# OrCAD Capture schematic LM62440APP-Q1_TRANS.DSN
size D; title: LM62440APP-Q1 Automotive 3-V to 36-V, 4-A, Low EMI; rev: 1.0; note: Datasheet:SNVSAW8B       EVM:SNVU622; note: Synchronous Step-Down Converter
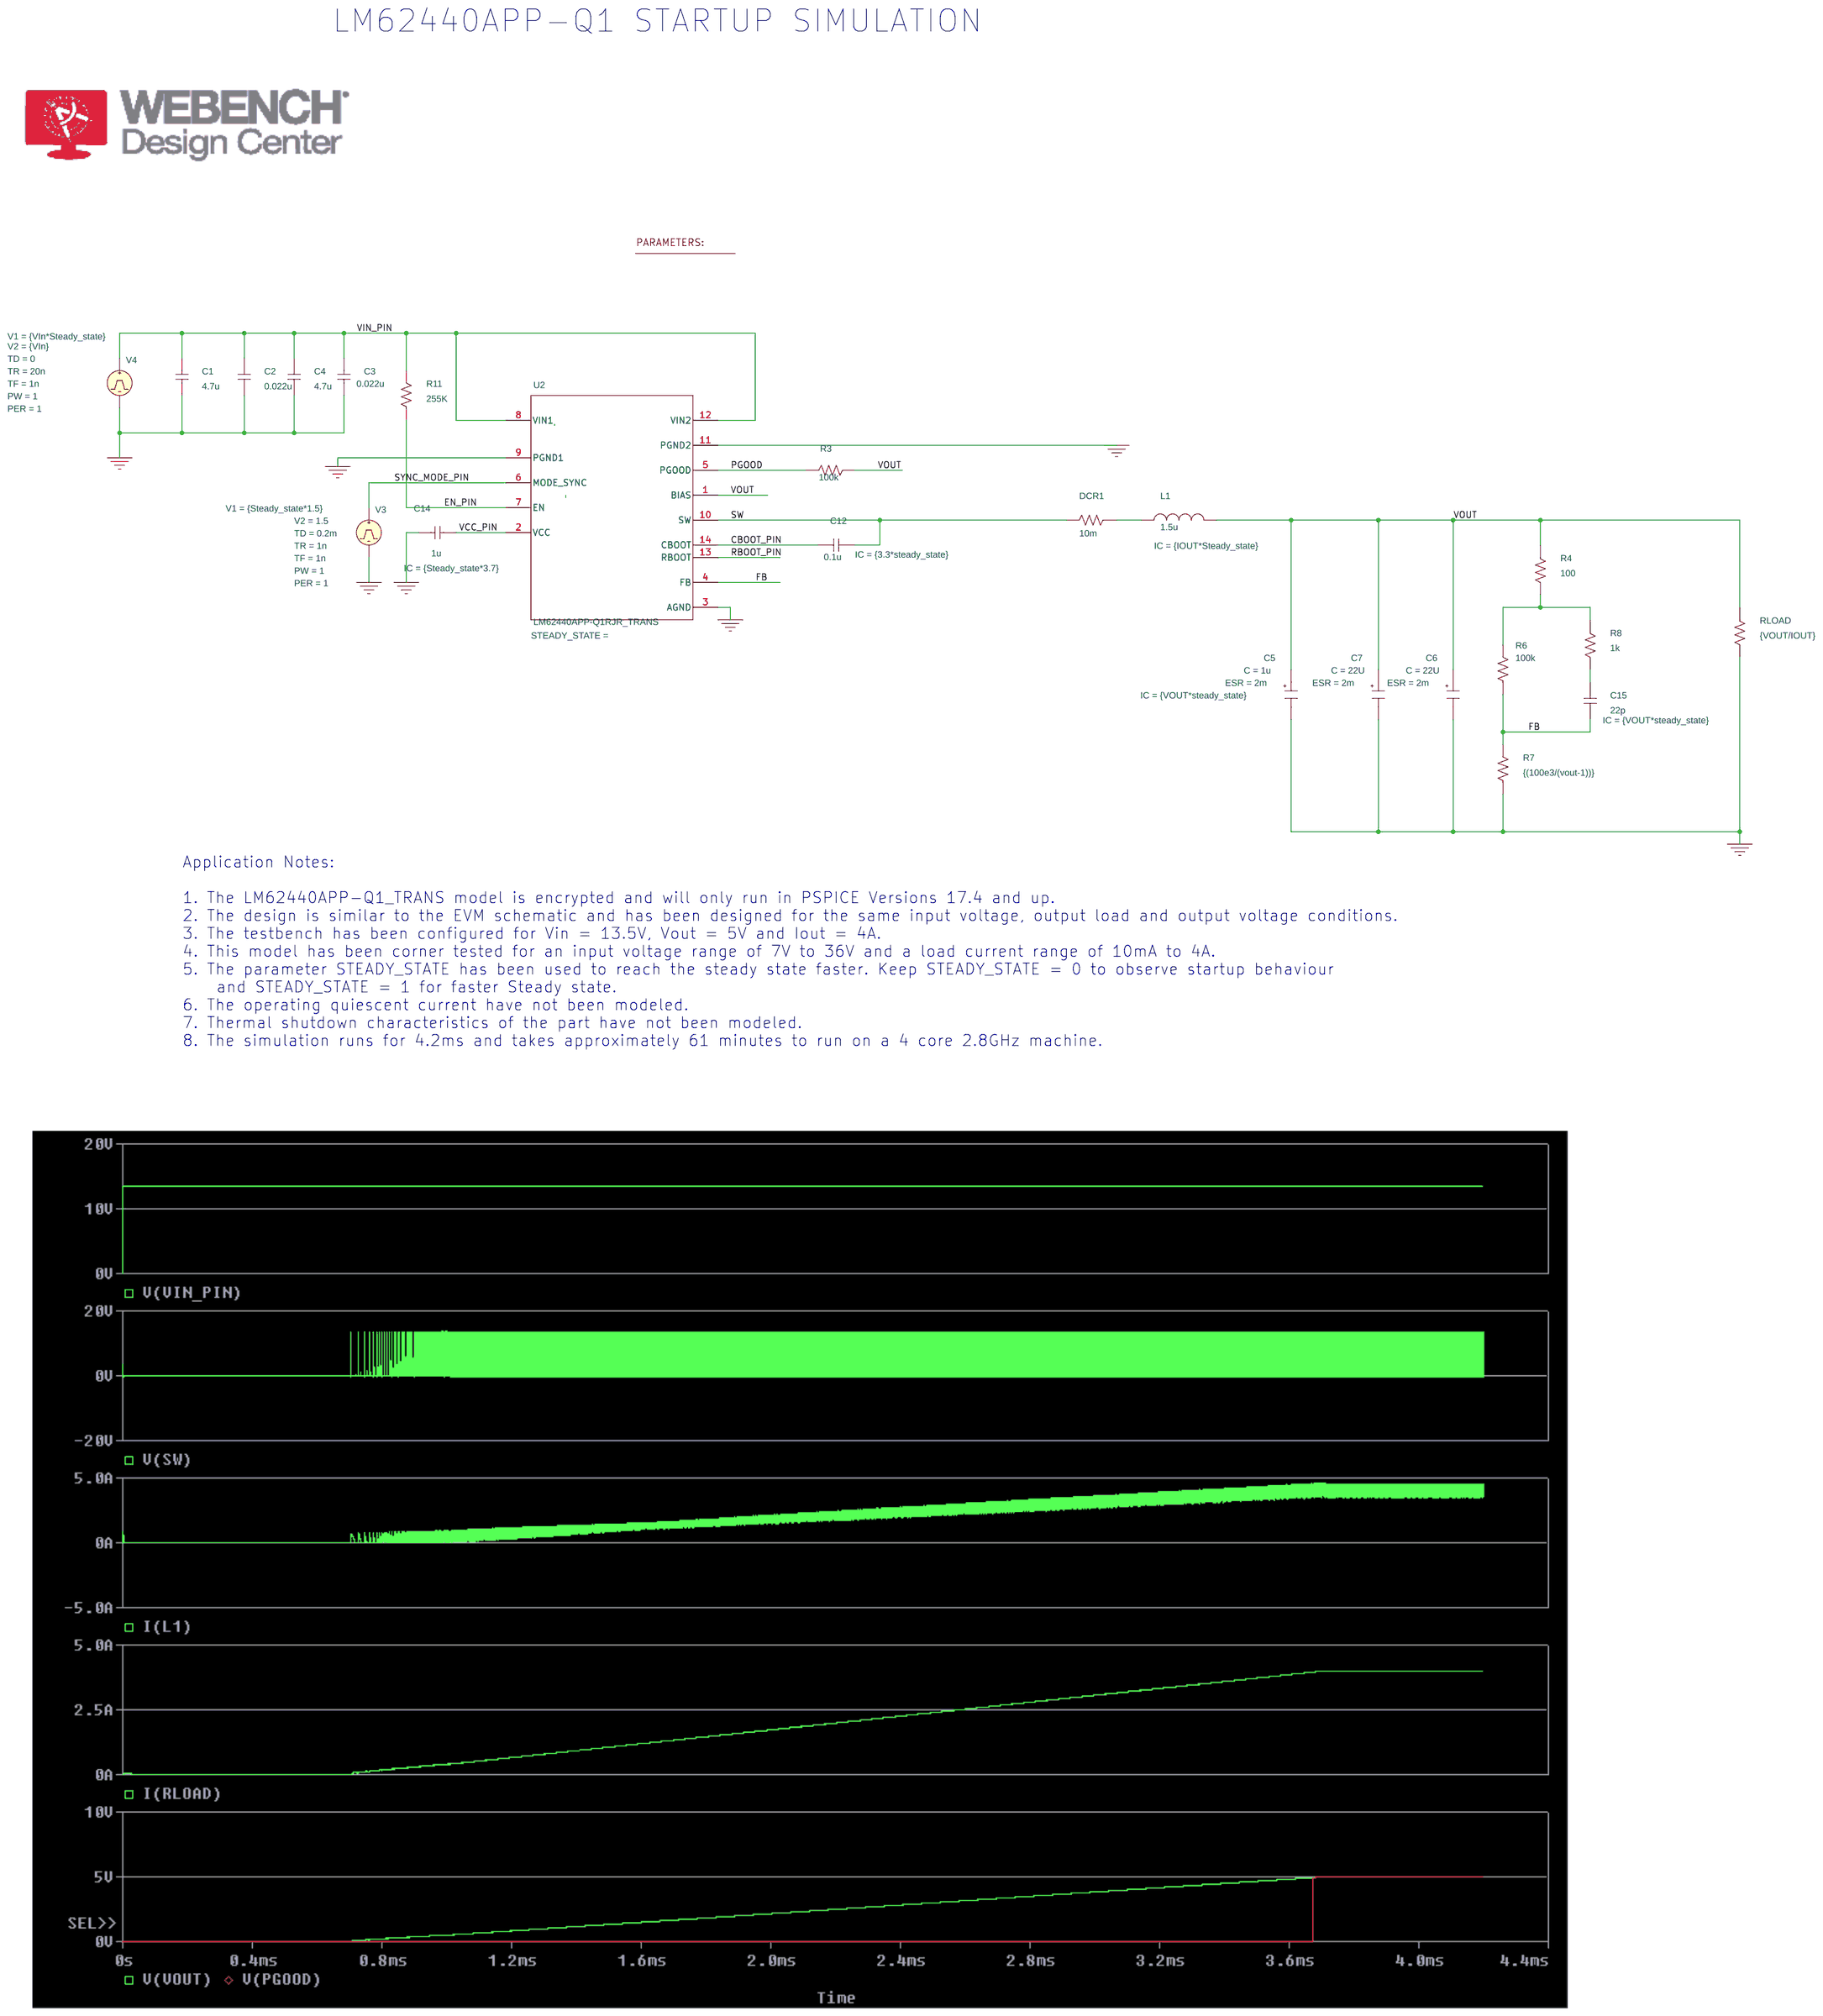
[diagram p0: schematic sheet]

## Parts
1  PARAM
C1  4.7u  [RAD/CK05]
C2  0.022u  [RAD/CK05]
C3  0.022u  [RAD/CK05]
C4  4.7u  [RAD/CK05]
C5  CESR
C6  CESR
C7  CESR
C12  0.1u  [RAD/CK05]
C14  1u  [RAD/CK05]
C15  22p  [RAD/CK05]
DCR1  10m  [AX/RC05]
L1  1.5u  [DISC/.350x.175/LS.200x.100/.034]
R3  100k  [AX/RC05]
R4  100  [AX/RC05]
R6  100k  [AX/RC05]
R7  {(100e3/(vout-1))}  [AX/RC05]
R8  1k  [AX/RC05]
R11  255K  [AX/RC05]
RLOAD  {VOUT/IOUT}  [AX/RC05]
U2  LM62440APP-Q1RJR_TRANS  [RJR0014A-MFG]
V3  VPULSE
V4  VPULSE

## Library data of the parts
1 = PARAM: Iout: 4; STEADY_STATE: 0; VIn: 13.5; Vout: 5
C1-C4 = C
C5 = CESR_0: C: 1u; ESR: 2m; IC: {VOUT*steady_state}; PSpiceTemplate: X^@REFDES %IN %OUT @MODEL PARAMS:  ?C|C=@C||C=100u|  ?ESR|ESR=@ESR||ESR=0.01| ?X|X=@X||X=2|  ?IC|IC=@IC||IC=2|; X: 1
C6 C7 = CESR_0: C: 22U; ESR: 2m; IC: {VOUT*steady_state}; PSpiceTemplate: X^@REFDES %IN %OUT @MODEL PARAMS:  ?C|C=@C||C=100u|  ?ESR|ESR=@ESR||ESR=0.01| ?X|X=@X||X=2|  ?IC|IC=@IC||IC=2|; X: 1
C12 = C: IC: {3.3*steady_state}
C14 = C: IC: {Steady_state*3.7}
C15 = C: IC: {VOUT*steady_state}
DCR1 R3 R4 R6-R8 R11 RLOAD = R
L1 = L: IC: {IOUT*Steady_state}
U2 = LM62440APP-Q1RJR_TRANS
V3 = VPULSE: PER: 1; PW: 1; TD: 0.2m; TF: 1n; TR: 1n; V1: {Steady_state*1.5}; V2: 1.5
V4 = VPULSE: PER: 1; PW: 1; TD: 0; TF: 1n; TR: 20n; V1: {VIn*Steady_state}; V2: {VIn}

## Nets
VCC_PIN: C14.1 U2.2(VCC)
VIN_PIN: C1.1 C2.1 C3.1 C4.1 R11.2 U2.8(VIN1) U2.12(VIN2) V4.1(+)
0: C1.2 C2.2 C3.2 C4.2 C5.2(OUT) C6.2(OUT) C7.2(OUT) C14.2 R7.1 RLOAD.2 U2.3(AGND) U2.9(PGND1) U2.11(PGND2) V3.2(-) V4.2(-)
CBOOT_PIN: C12.1 U2.14(CBOOT)
EN_PIN: R11.1 U2.7(EN)
FB: C15.2 R6.1 R7.2 U2.4(FB)
PGOOD: R3.1 U2.5(PGOOD)
RBOOT_PIN: U2.13(RBOOT)
SW: C12.2 DCR1.2 U2.10(SW)
SYNC_MODE_PIN: U2.6(MODE_SYNC) V3.1(+)
VOUT: C5.1(IN) C6.1(IN) C7.1(IN) L1.2 R3.2 R4.1 RLOAD.1 U2.1(BIAS)
N16770929: DCR1.1 L1.1
N16787690: R4.2 R6.2 R8.1
N16787736: C15.1 R8.2

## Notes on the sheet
- LM62440APP-Q1 STARTUP SIMULATION
- Application Notes:
  1. The LM62440APP-Q1_TRANS model is encrypted and will only run in PSPICE Versions 17.4 and up.
  2. The design is similar to the EVM schematic and has been designed for the same input voltage, output load and output voltage conditions.
  3. The testbench has been configured for Vin = 13.5V, Vout = 5V and Iout = 4A.
  4. This model has been corner tested for an input voltage range of 7V to 36V and a load current range of 10mA to 4A.
  5. The parameter STEADY_STATE has been used to reach the steady state faster. Keep STEADY_STATE = 0 to observe startup behaviour
      and STEADY_STATE = 1 for faster Steady state.
  6. The operating quiescent current have not been modeled.
  7. Thermal shutdown characteristics of the part have not been modeled.
  8. The simulation runs for 4.2ms and takes approximately 61 minutes to run on a 4 core 2.8GHz machine.
